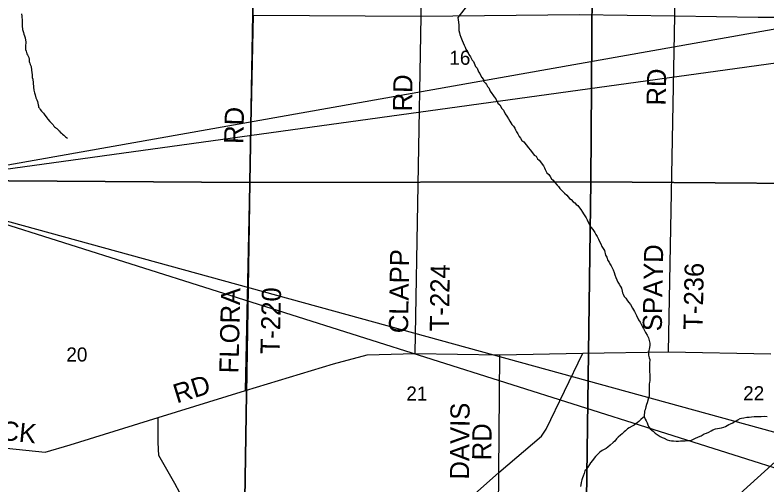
# Model space of a CAD drawing. Extents: x 36.7 to 70.7, y 0 to 22.
# Drawn here: x 42.544 to 44.771, y 16.011 to 17.404 of the extents above; entities that cross this region are included whole.
import ezdxf

# ---------------------------------------------------------------- set-up
doc = ezdxf.new("R2010")
doc.units = 0
for name, color, linetype in [('GM_X_County_Road', 7, 'Continuous'), ('GM_X_County_Road_Text', 7, 'Continuous'), ('GM_X_Minor_River', 7, 'Continuous'), ('GM_X_Rail_Line', 7, 'Continuous'), ('GM_X_Section', 7, 'Continuous'), ('GM_X_Section_Text', 7, 'Continuous'), ('GM_X_Township_Road', 7, 'Continuous'), ('GM_X_Township_Road_Text', 7, 'Continuous'), ('SH_Text', 7, 'Continuous')]:
    doc.layers.add(name, color=color, linetype=linetype)

msp = doc.modelspace()

# ---------------------------------------------------------------- linework, layer by layer
at = {"layer": 'GM_X_County_Road'}
for p, q in [((44.2264, 16.4016), (44.4801, 16.4056)), ((44.4801, 16.4056), (44.7825, 16.4))]:
    msp.add_line(p, q, dxfattribs=at)
for points in [[(43.2502, 17.4045), (43.7467, 17.4014), (44.216, 17.4059), (44.498, 17.4024)], [(44.498, 17.4024), (44.7452, 17.3981), (45.1979, 17.398), (45.206, 17.3979)], [(42.2224, 16.1536), (42.32, 16.1431), (42.4892, 16.1233), (42.6333, 16.1077), (42.7073, 16.1297), (42.9675, 16.211), (43.2265, 16.2915), (43.4871, 16.3698), (43.587, 16.3971), (43.7291, 16.4012), (43.9799, 16.3965), (44.2264, 16.4016)], [(43.977, 16.0478), (44.1032, 16.1559), (44.1172, 16.1762), (44.2264, 16.4016)], [(42.7218, 14.9518), (42.9578, 15.1566), (43.2165, 15.3796), (43.5905, 15.714), (43.7102, 15.8162), (43.9134, 15.9918), (43.977, 16.0478)]]:
    msp.add_lwpolyline(points, dxfattribs=at)
at = {"layer": 'GM_X_Minor_River'}
for points in [[(43.8845, 17.4333), (43.8557, 17.3975)], [(42.5631, 17.4076), (42.5637, 17.4011), (42.564, 17.3962), (42.5647, 17.3924), (42.565, 17.3882), (42.5653, 17.3848), (42.565, 17.3719), (42.5663, 17.362), (42.5666, 17.3582), (42.5688, 17.3525), (42.5698, 17.3479), (42.5716, 17.3425), (42.5741, 17.3364), (42.5751, 17.3299), (42.5757, 17.3246), (42.5756, 17.3201), (42.5752, 17.3163), (42.5751, 17.3133), (42.5746, 17.3064), (42.5749, 17.3026), (42.5771, 17.2973), (42.5788, 17.2893), (42.581, 17.2866), (42.5832, 17.2828), (42.5846, 17.2782), (42.5856, 17.2732), (42.5859, 17.2668), (42.587, 17.2641), (42.5873, 17.2614), (42.5887, 17.258), (42.5894, 17.2553), (42.5913, 17.2519), (42.5925, 17.2408), (42.5945, 17.2275), (42.5951, 17.2192), (42.5969, 17.2146), (42.5974, 17.2036), (42.5983, 17.191), (42.5996, 17.1819), (42.6017, 17.1735), (42.6035, 17.1682), (42.6056, 17.1586), (42.6089, 17.1533), (42.6103, 17.1483), (42.6117, 17.1426), (42.6124, 17.138), (42.6131, 17.135), (42.6137, 17.1308), (42.6159, 17.1281), (42.6185, 17.1239), (42.6222, 17.1196), (42.6252, 17.1162), (42.6277, 17.1131), (42.6299, 17.11), (42.6322, 17.1073), (42.6362, 17.103), (42.6381, 17.1), (42.6414, 17.0957), (42.6469, 17.0892), (42.6569, 17.0787), (42.6584, 17.0749), (42.661, 17.073), (42.664, 17.0714), (42.6654, 17.0687)], [(43.8556, 17.3979), (43.8566, 17.3888), (43.8574, 17.3838), (43.8584, 17.3736), (43.8583, 17.3671), (43.859, 17.3588), (43.8604, 17.3519), (43.8619, 17.3466), (43.8648, 17.3386), (43.8689, 17.3287), (43.8714, 17.3222), (43.8744, 17.3149), (43.877, 17.3092), (43.8792, 17.3031), (43.884, 17.2959), (43.8885, 17.2878), (43.893, 17.2802), (43.8982, 17.271), (43.9023, 17.2664), (43.9082, 17.252), (43.9127, 17.2466), (43.9171, 17.2359), (43.9208, 17.2313), (43.9257, 17.2206), (43.9313, 17.2134), (43.932, 17.2088), (43.9376, 17.2027), (43.9409, 17.1981), (43.9432, 17.1927), (43.9477, 17.1881), (43.9517, 17.1782), (43.9562, 17.1721), (43.9592, 17.1675), (43.9633, 17.1618), (43.9678, 17.1557), (43.9745, 17.1431), (43.9797, 17.1381), (43.9856, 17.127), (43.9905, 17.122), (43.9961, 17.1113), (44.0009, 17.1044), (44.0054, 17.0968), (44.0095, 17.0895), (44.0151, 17.08), (44.0203, 17.0746), (44.0244, 17.0685), (44.0267, 17.0639), (44.0296, 17.0582), (44.0337, 17.0517), (44.0378, 17.0445), (44.0415, 17.0391), (44.0453, 17.0326), (44.0509, 17.028), (44.058, 17.0192), (44.0651, 17.0108), (44.07, 17.005), (44.0741, 16.9997), (44.0819, 16.9893), (44.0872, 16.9855), (44.0921, 16.9782), (44.0966, 16.974), (44.1003, 16.9694), (44.1059, 16.9617), (44.1093, 16.9568), (44.1122, 16.9518), (44.1145, 16.9468), (44.1193, 16.9365), (44.1253, 16.9312), (44.1294, 16.9254), (44.1327, 16.9189), (44.1376, 16.9151), (44.1432, 16.9078), (44.1496, 16.9002), (44.1541, 16.8955), (44.1578, 16.8902), (44.1642, 16.8837), (44.1713, 16.8764), (44.1784, 16.8702), (44.1863, 16.8607), (44.1912, 16.8576), (44.1976, 16.8507), (44.2025, 16.848), (44.2062, 16.843), (44.2107, 16.8399), (44.2163, 16.8326), (44.2197, 16.8277), (44.2245, 16.82), (44.2279, 16.815), (44.2316, 16.8089), (44.2357, 16.8032), (44.2387, 16.7967), (44.2427, 16.7883), (44.2461, 16.7822), (44.2498, 16.775), (44.2554, 16.7684), (44.261, 16.7593), (44.2647, 16.7535), (44.2681, 16.7474), (44.2725, 16.7398), (44.2751, 16.7329), (44.2792, 16.726)], [(42.6654, 17.0687), (42.6681, 17.0675), (42.6736, 17.0617), (42.6762, 17.0598), (42.6777, 17.0567), (42.6818, 17.054), (42.6844, 17.0516), (42.6885, 17.0481), (42.6933, 17.0435), (42.6959, 17.0412), (42.6993, 17.0388)], [(44.2792, 16.726), (44.2825, 16.7184), (44.2866, 16.7123), (44.29, 16.7058), (44.2932, 16.6925), (44.2966, 16.6864), (44.3003, 16.6765), (44.3036, 16.6719), (44.3058, 16.6669), (44.3096, 16.6612), (44.3125, 16.6543), (44.3155, 16.6486), (44.3184, 16.641), (44.321, 16.6337), (44.3236, 16.6261), (44.3269, 16.6196), (44.3295, 16.6124), (44.3332, 16.6067), (44.3377, 16.5994), (44.3403, 16.594), (44.3425, 16.5857), (44.3439, 16.5807), (44.3458, 16.5762), (44.3484, 16.5697), (44.3529, 16.5651), (44.3581, 16.5574), (44.3626, 16.5524), (44.3674, 16.5459), (44.3734, 16.5356), (44.3786, 16.5257), (44.3823, 16.5196), (44.3853, 16.5139), (44.3912, 16.5001), (44.3957, 16.4936), (44.3986, 16.4879), (44.4031, 16.4799), (44.4053, 16.4749), (44.4083, 16.4688), (44.412, 16.4635), (44.4168, 16.4547), (44.4202, 16.4474), (44.4227, 16.439), (44.4249, 16.4314), (44.4249, 16.4257), (44.4236, 16.4185), (44.4204, 16.4049), (44.42, 16.3958), (44.4221, 16.3882), (44.424, 16.3825), (44.4239, 16.3715), (44.4234, 16.3662), (44.4232, 16.3476), (44.4242, 16.3377), (44.4249, 16.3308), (44.4245, 16.3248), (44.424, 16.3198), (44.4236, 16.3153), (44.4228, 16.31), (44.422, 16.3054), (44.4229, 16.2906), (44.4228, 16.2823), (44.4224, 16.2747), (44.4204, 16.269), (44.4168, 16.2546), (44.4141, 16.2493), (44.4125, 16.2421), (44.4105, 16.2338), (44.409, 16.2293), (44.4089, 16.2247), (44.4077, 16.2194), (44.408, 16.2141), (44.411, 16.2065), (44.4132, 16.2011), (44.4162, 16.1954), (44.4187, 16.1893), (44.4206, 16.1847), (44.4254, 16.1771), (44.4345, 16.1705), (44.4401, 16.1648), (44.4457, 16.1602), (44.4551, 16.1551), (44.4612, 16.1513), (44.4668, 16.1497), (44.4755, 16.1447), (44.4831, 16.1427), (44.4884, 16.1419), (44.4948, 16.1414), (44.502, 16.1406), (44.5096, 16.1409), (44.5153, 16.142), (44.5218, 16.1419), (44.529, 16.1422), (44.5388, 16.1425), (44.5457, 16.1432), (44.5537, 16.1469), (44.5582, 16.1483), (44.5689, 16.1539), (44.5762, 16.1569), (44.5853, 16.1628), (44.5922, 16.1647), (44.5991, 16.1676)], [(44.4078, 16.2132), (44.405, 16.2111), (44.3977, 16.2047), (44.3923, 16.1991), (44.3873, 16.1953), (44.3827, 16.1923), (44.3781, 16.1882), (44.3724, 16.1849), (44.3636, 16.1804), (44.3579, 16.177), (44.3525, 16.1718), (44.348, 16.1688), (44.3426, 16.1624), (44.3376, 16.1583), (44.3303, 16.1523), (44.3253, 16.1478), (44.3211, 16.141), (44.3157, 16.1369), (44.3065, 16.1286), (44.3, 16.1226), (44.295, 16.1193), (44.2893, 16.1159), (44.2836, 16.1129), (44.2767, 16.1077), (44.2721, 16.1047), (44.2683, 16.0998), (44.2633, 16.0957), (44.2591, 16.09), (44.2541, 16.0836), (44.2487, 16.0765), (44.2452, 16.0712), (44.2405, 16.064), (44.2374, 16.058), (44.2321, 16.0524), (44.2297, 16.0452), (44.227, 16.0369), (44.225, 16.0319), (44.223, 16.0259), (44.2207, 16.0183), (44.2198, 16.0115), (44.219, 16.0062)], [(44.5991, 16.1676), (44.6059, 16.171), (44.6113, 16.174), (44.6193, 16.1773), (44.6364, 16.1805), (44.644, 16.1827), (44.6489, 16.1846), (44.6585, 16.1902), (44.6638, 16.192), (44.6703, 16.1953), (44.6749, 16.1987), (44.6802, 16.2009), (44.6852, 16.2043), (44.6917, 16.2076), (44.6963, 16.2091), (44.7027, 16.2102), (44.7118, 16.212), (44.719, 16.2119), (44.7259, 16.2126), (44.7339, 16.2136), (44.7399, 16.214), (44.7471, 16.2135), (44.7547, 16.2138), (44.7646, 16.2145), (44.7722, 16.2144)]]:
    msp.add_lwpolyline(points, dxfattribs=at)
at = {"layer": 'GM_X_Rail_Line'}
msp.add_lwpolyline([(42.5932, 14.0969), (42.6018, 14.1045), (42.9057, 14.3723), (43.2092, 14.6439), (43.5174, 14.9236), (43.8818, 15.2533), (44.2007, 15.5398), (44.9423, 16.2118), (45.4899, 16.7019), (45.5934, 16.801)], dxfattribs=at)
at = {"layer": 'GM_X_Section'}
for points in [[(43.2576, 17.9081), (43.2397, 16.908), (42.2388, 16.9146), (42.2487, 17.912)], [(44.2567, 17.9094), (44.2493, 16.9097), (43.2397, 16.908), (43.2576, 17.9081)], [(45.2484, 17.9213), (45.2325, 16.9015), (44.2493, 16.9097), (44.2567, 17.9094)], [(43.2397, 16.908), (43.2232, 15.9056), (42.2098, 15.9172), (42.2388, 16.9146)], [(44.2493, 16.9097), (44.2362, 15.8944), (43.2232, 15.9056), (43.2397, 16.908)], [(45.2325, 16.9015), (45.2216, 15.8945), (44.2362, 15.8944), (44.2493, 16.9097)]]:
    msp.add_lwpolyline(points, close=True, dxfattribs=at)
at = {"layer": 'GM_X_Township_Road'}
for p, q in [((43.2265, 16.2915), (43.2502, 17.4045)), ((43.7291, 16.4012), (43.7467, 17.4014))]:
    msp.add_line(p, q, dxfattribs=at)
for points in [[(43.7467, 17.4014), (43.7552, 18.0731), (43.7554, 18.082)], [(44.4801, 16.4056), (44.498, 17.4024), (44.5009, 17.6179), (44.5064, 17.8635), (44.5066, 17.8735)], [(43.973, 15.6102), (43.977, 16.0478), (43.9799, 16.3965)], [(44.2818, 15.3016), (44.1278, 15.4892), (44.0315, 15.5895), (44.0183, 15.5966), (44.0021, 15.6014), (43.9968, 15.603), (43.9915, 15.6057), (43.973, 15.6102), (43.8985, 15.6289), (43.5905, 15.714), (43.5074, 15.7438), (43.4741, 15.7516), (43.2738, 15.762), (43.1602, 15.8481), (43.0617, 15.9325), (43.0175, 16.0153), (42.9702, 16.0985), (42.9678, 16.1373), (42.9675, 16.211)]]:
    msp.add_lwpolyline(points, dxfattribs=at)
at = {"layer": 'SH_Text'}
for points in [[(47.1799, 17.7861), (42.2435, 16.9102), (47.1799, 17.5925)], [(42.2513, 16.8669), (47.0528, 15.5458), (47.0528, 15.3449)]]:
    msp.add_lwpolyline(points, close=True, dxfattribs=at)

# ---------------------------------------------------------------- texts
at = {"layer": 'GM_X_County_Road_Text'}
for s, rotation, p in [('RD', 17.1766, (43.023, 16.2524)), ('LIMERICK', 354.3034, (42.2468, 16.1699))]:
    msp.add_text(s, height=0.05682, rotation=rotation, dxfattribs=at).set_placement(p)
at = {"layer": 'GM_X_Section_Text'}
for s, p in [('16', (43.8305, 17.2569)), ('20', (42.6959, 16.3769)), ('21', (43.703, 16.261)), ('22', (44.7009, 16.2618))]:
    msp.add_text(s, height=0.04186, rotation=0, dxfattribs=at).set_placement(p)
at = {"layer": 'GM_X_Township_Road_Text'}
for s, rotation, p in [('RD', 89.0128, (44.4715, 17.1356)), ('RD', 89.0128, (43.7198, 17.1181)), ('RD', 88.5175, (43.2198, 17.0216)), ('SPAYD', 88.9513, (44.4598, 16.4664)), ('CLAPP', 89.1157, (43.7081, 16.4605)), ('T-224', 89.1579, (43.8291, 16.4662)), ('T-236', 88.8773, (44.5807, 16.4707)), ('FLORA', 88.7408, (43.2056, 16.3415)), ('T-220', 88.5957, (43.3274, 16.3978)), ('DAVIS', 89.5493, (43.8889, 16.0267)), ('RD', 89.5045, (43.9548, 16.0837))]:
    msp.add_text(s, height=0.05682, rotation=rotation, dxfattribs=at).set_placement(p)

doc.saveas('drawing.dxf')
